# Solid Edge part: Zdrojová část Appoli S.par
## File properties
Title: Zdrojová část Appoli S
Author: petr.kostka
Keywords: ---
Template: Part Robe 03_24.par
Last saved by: petr.kostka
Revision: 64
Application: Solid Edge
Company: 19030929-01M
Hustota: 2680,000 kg/m^3
Přesnost: 0,990
Username: petr.kostka
Typ obsahu dokumentu: 0
Material: LM6 - slitina hliníku
Face Style: Model Default
Fill Style: Normal
Virtual Style: Normal
Skupiny: Slitiny hliníku
LibraryName: Robe knihovna - Konstrukce
Coef. of Thermal Exp: 0.0
Thermal Conductivity: 0.0
Specific Heat: 0.0
Modulus of Elasticity: 0.0
Poisson's Ratio: 0.0
Yield Stress: 0.0
Ultimate Stress: 0.0
Elongation: 0.0
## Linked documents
st Appoli S.par
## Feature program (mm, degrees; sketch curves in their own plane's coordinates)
part copy "KopírovanáSoučást_2"
sketch for "Vysunutí_1" plane through (0, 54.7, 0.0002) normal (0, 1, 0) x-axis (0, 0, 1)
  arc centre (42.4998, 42.5) radius 14 from (42.4998, 56.5) to (56.4998, 42.5) cw
  line (56.4998, -42.5) -> (56.4998, 42.5)
  arc centre (42.4998, -42.5) radius 14 from (56.4998, -42.5) to (42.4998, -56.5) cw
  line (-42.5002, -56.5) -> (42.4998, -56.5)
  arc centre (-42.5002, -42.5) radius 14 from (-42.5002, -56.5) to (-56.5002, -42.5) cw
  line (-56.5002, 42.5) -> (-56.5002, -42.5)
  arc centre (-42.5002, 42.5) radius 14 from (-56.5002, 42.5) to (-42.5002, 56.5) cw
  line (42.4998, 56.5) -> (-42.5002, 56.5)
extrude "Vysunutí_1" add finite 54 along -normal
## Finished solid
Body 1: solid body, 360 faces, 710 edges, 352 vertices.
  Faces by surface: blend 120, sphere 112, cylinder 53, plane 31, swept 20, cone 8, spline 8, torus 8
  Edges by curve: circle 354, intersection 240, line 96, curve on surface 12, ellipse 8
Bounding box of the edges (mm; curved faces can reach further): 121.175 x 54.700 x 121.492, from (-60.5877, 0, -60.746) to (60.5877, 54.7, 60.7463).
Cylindrical faces by radius (mm): R0.5 x48, R2.655 x4, R5.75 x1
Conical faces (half-angle, radius in mm at the cone's reference point): 1.0959 deg R14.5272 x4, 1.0974 deg R14.5525 x4
Toroidal faces (ring radius, tube radius in mm): R14.0619 r0.5 x4, R15.0906 r0.5 x4
Spherical faces by radius (mm): R0.5 x112
Planar faces by outward normal: +y 1, -y 6, oblique 24
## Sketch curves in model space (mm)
arc centre (-42.5, 54.7, 42.5) radius 14 from (-42.5, 54.7, 56.5) through (-52.6832, 54.7, 52.1074) to (-56.5, 54.7, 42.5)
line (-42.5, 54.7, 56.5) -> (42.5, 54.7, 56.5)
arc centre (42.5, 54.7, 42.5) radius 14 from (56.5, 54.7, 42.5) through (52.1074, 54.7, 52.6832) to (42.5, 54.7, 56.5)
line (56.5, 54.7, 42.5) -> (56.5, 54.7, -42.5)
arc centre (42.5, 54.7, -42.5) radius 14 from (42.5, 54.7, -56.5) through (52.6832, 54.7, -52.1074) to (56.5, 54.7, -42.5)
line (42.5, 54.7, -56.5) -> (-42.5, 54.7, -56.5)
arc centre (-42.5, 54.7, -42.5) radius 14 from (-56.5, 54.7, -42.5) through (-52.1074, 54.7, -52.6832) to (-42.5, 54.7, -56.5)
line (-56.5, 54.7, -42.5) -> (-56.5, 54.7, 42.5)
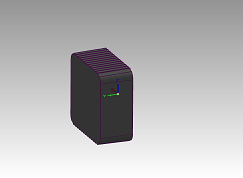
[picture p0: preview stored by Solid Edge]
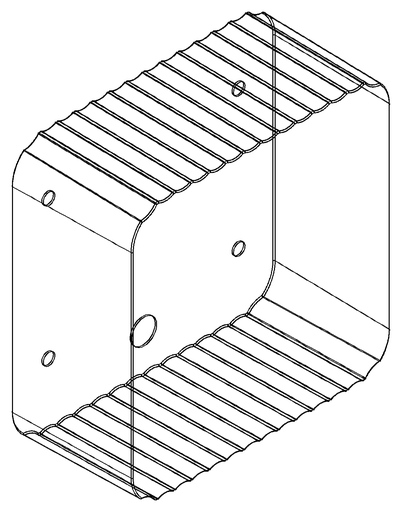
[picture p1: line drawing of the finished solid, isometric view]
